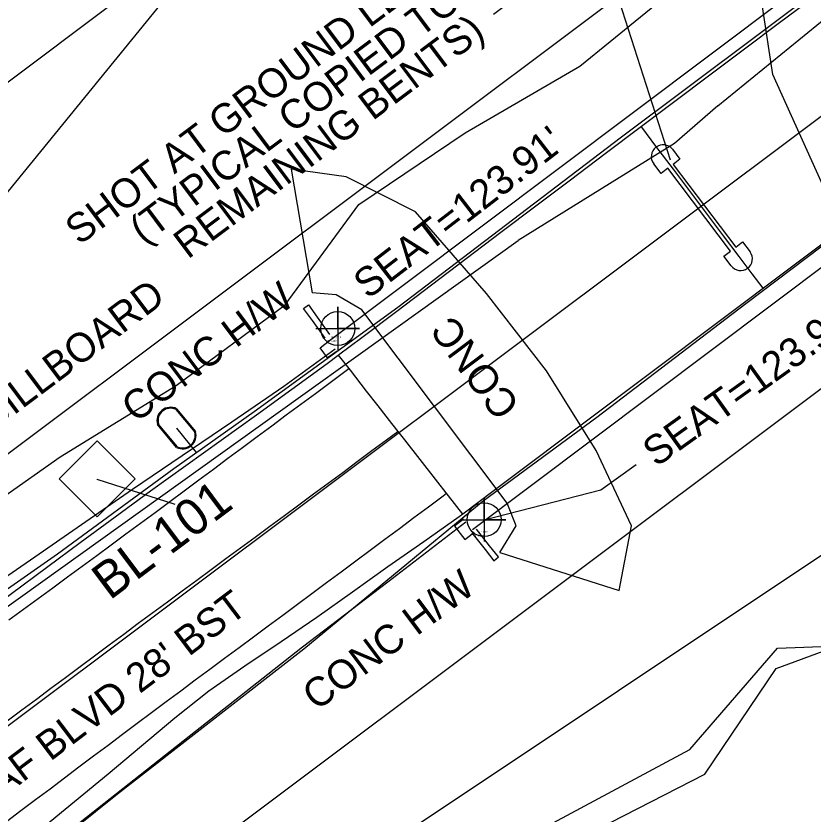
# Model space of a CAD drawing. Extents: x 2186615 to 2188822, y 629899 to 631820.
# Drawn here: x 2187538.9 to 2187648.6, y 630666.8 to 630776.8 of the extents above; entities that cross this region are included whole.
import ezdxf

# ---------------------------------------------------------------- set-up
doc = ezdxf.new("R2010")
doc.units = 0
for name, color, linetype in [('CTL Secondary Horizontal and Vertical CELL', 7, 'Continuous'), ('CTL Secondary Horizontal and Vertical Text', 7, 'Continuous'), ('CTL Vertical Benchmark Leader', 7, 'Continuous'), ('Exist Environmental Wetland Boundary', 7, 'Continuous'), ('Exist Guardrail', 7, 'Continuous'), ('Exist Horizontal Alignment', 7, 'Continuous'), ('Exist Hydro Jurisdictional Stream or Body of Water', 7, 'Continuous'), ('Exist Hydro Stream or Body of Water', 7, 'Continuous'), ('Exist Other Culture Area Outline', 7, 'Continuous'), ('Exist Other Culture Area Outline Leader', 7, 'Continuous'), ('Exist Other Culture Area Outline Text', 7, 'Continuous'), ('Exist Other Culture Sign Text', 7, 'Continuous'), ('Exist Right of Way Easement Line', 7, 'Continuous'), ('Exist Right of Way Line', 7, 'Continuous'), ('Exist Roads Curbs', 7, 'Continuous'), ('Exist Roads EOP', 7, 'Continuous'), ('Exist Roads EOP Text', 7, 'Continuous'), ('Exist Roads EOT', 7, 'Continuous'), ('Exist Structure Major Bridge Seam', 7, 'Continuous'), ('Exist Structure Major Bridge Seat Cogo Point CELL', 7, 'Continuous'), ('Exist Structure Major Bridge Seat Leader', 7, 'Continuous'), ('Exist Structure Major Bridge Seat Top Elevation', 7, 'Continuous'), ('Exist Structure Major Bridge WW', 7, 'Continuous'), ('Exist Structure Major Bridge WW Cogo Comment', 7, 'Continuous'), ('Exist Structure Major Bridge WW Text', 7, 'Continuous'), ('Exist Structure Major Deck Tunnel Box Culvert', 7, 'Continuous'), ('Exist Utilities Gas UG Line SUE LOS B', 7, 'Continuous'), ('Exist Utilities Sanitary Sewer Forced Main SUE LOS B', 7, 'Continuous'), ('Exist Utilities Telephone UG FO SUE LOS B', 7, 'Continuous'), ('Exist Utilities Water Meter CELL', 7, 'Continuous'), ('Exist Utilities Water UG Line SUE LOS B', 7, 'Continuous')]:
    doc.layers.add(name, color=color, linetype=linetype)

msp = doc.modelspace()

# ---------------------------------------------------------------- linework, layer by layer
at = {"layer": 'CTL Secondary Horizontal and Vertical CELL'}
msp.add_line((2187550.03, 630712.99), (2187550.03, 630712.99), dxfattribs=at)
msp.add_lwpolyline([(2187544.82, 630713.01), (2187550.06, 630718.25), (2187555.31, 630713), (2187550.07, 630707.76)], close=True, dxfattribs=at)
at = {"layer": 'CTL Vertical Benchmark Leader'}
msp.add_line((2187550.03, 630712.99), (2187560.75, 630709.52), dxfattribs=at)
at = {"layer": 'Exist Environmental Wetland Boundary'}
msp.add_lwpolyline([(2187317.91, 630575.27), (2187346.42, 630590.06), (2187358.05, 630607.86), (2187375.02, 630623.81), (2187367.38, 630649.06), (2187358.56, 630671.73), (2187359.61, 630693.05), (2187383.09, 630714.06), (2187423.1, 630746.78), (2187442.69, 630752.31), (2187457.31, 630748.34), (2187478.61, 630729.85), (2187488.29, 630719.76), (2187508.8, 630730.52), (2187517.08, 630724.68), (2187534.78, 630748.93), (2187558.89, 630778.43), (2187554.21, 630796.36), (2187540.11, 630831.28), (2187531.55, 630860.27), (2187515.41, 630893.02), (2187492.5, 630933.33), (2187481.79, 630966.82), (2187476.92, 630985.98)], dxfattribs=at)
at = {"layer": 'Exist Guardrail'}
for points in [[(2187492.14, 630668.93), (2187506.78, 630678.73), (2187517.34, 630685.81), (2187530.14, 630694.49), (2187541.5, 630702.26), (2187554.93, 630711.6), (2187568.6, 630720.88), (2187575.75, 630725.78), (2187582.83, 630730.92)], [(2187600.82, 630707.03), (2187590.08, 630698.8), (2187578.34, 630689.84), (2187562.72, 630677.51), (2187547.73, 630665.68), (2187531.87, 630653.17), (2187514.82, 630639.34), (2187500.32, 630627.65), (2187485.34, 630615.46), (2187477.41, 630609.1), (2187466.89, 630601.03), (2187451.76, 630589.34), (2187434.11, 630575.84), (2187413.64, 630560.33)]]:
    msp.add_lwpolyline(points, dxfattribs=at)
at = {"layer": 'Exist Horizontal Alignment'}
msp.add_line((2187136.41, 630378.11), (2188520.86, 631416.04), dxfattribs=at)
at = {"layer": 'Exist Hydro Jurisdictional Stream or Body of Water'}
for points in [[(2187685.21, 630670.03), (2187676.46, 630688.92), (2187667.73, 630709.8), (2187657.08, 630737.8), (2187643.12, 630768.72), (2187641.56, 630778.99)], [(2187449.56, 630557.04), (2187457.67, 630561.55), (2187469.6, 630560.19), (2187477.83, 630568.81), (2187483.29, 630570.83), (2187487.27, 630573.49), (2187494.84, 630580), (2187501.28, 630583.62), (2187529.01, 630602.42), (2187543.47, 630612.86), (2187569.07, 630628.39), (2187588.84, 630647.49), (2187600.3, 630658.9), (2187631.69, 630675.75), (2187643.77, 630689.68), (2187651.01, 630689.99), (2187663.15, 630692.5)], [(2187633.75, 630672.36), (2187643.56, 630686.91), (2187650.93, 630689.62), (2187663.86, 630688.82), (2187677.92, 630676.75), (2187685.21, 630670.03)], [(2187447.83, 630554.37), (2187455.66, 630557.6), (2187469.6, 630555.05), (2187473.86, 630558.86), (2187485.6, 630566.69), (2187490.63, 630573.04), (2187490.78, 630573.03), (2187503.45, 630582.34), (2187528.93, 630598.21), (2187547.35, 630610.71), (2187554.69, 630615.02), (2187566.17, 630622.44), (2187570.59, 630621.55), (2187578.03, 630632.5), (2187587.26, 630641.63), (2187602.46, 630652.89), (2187618.95, 630664.76), (2187633.75, 630672.36)]]:
    msp.add_lwpolyline(points, dxfattribs=at)
at = {"layer": 'Exist Hydro Stream or Body of Water'}
msp.add_line((2187643.56, 630686.91), (2187650.93, 630689.62), dxfattribs=at)
at = {"layer": 'Exist Other Culture Area Outline'}
for p, q in [((2187629.28, 630758.4), (2187630.31, 630757.04)), ((2187627.71, 630755.07), (2187626.7, 630756.41)), ((2187630.31, 630757.04), (2187629.37, 630756.33)), ((2187629.37, 630756.33), (2187638, 630744.94)), ((2187628.66, 630755.79), (2187627.71, 630755.07)), ((2187637.29, 630744.39), (2187628.66, 630755.79)), ((2187638, 630744.94), (2187638.95, 630745.65)), ((2187638.95, 630745.65), (2187639.98, 630744.29)), ((2187636.35, 630743.68), (2187637.29, 630744.39)), ((2187637.36, 630742.34), (2187636.35, 630743.68)), ((2187601.49, 630705.27), (2187601.97, 630705.66))]:
    msp.add_line(p, q, dxfattribs=at)
for points in [[(2187605.53, 630702.86), (2187621.96, 630697.63), (2187623.64, 630706.53), (2187618.78, 630716.92), (2187611.96, 630727.88), (2187603.68, 630738.56), (2187593.88, 630749.79), (2187584.36, 630754.61), (2187576.76, 630755.68), (2187579.69, 630738.64)], [(2187605.53, 630702.86), (2187607.77, 630706.55), (2187606.54, 630709.67), (2187586.53, 630736.3), (2187582.99, 630738.34), (2187579.69, 630738.64)], [(2187581.78, 630729.66), (2187580.75, 630731.05), (2187582.05, 630732.05)], [(2187599.25, 630706.5), (2187600.69, 630704.66), (2187601.49, 630705.27)]]:
    msp.add_lwpolyline(points, dxfattribs=at)
for centre, start, end in [((2187628, 630757.39), 38.2035, 217.1439), ((2187638.66, 630743.33), 217.1439, 36.0842)]:
    msp.add_arc(centre, 1.63, start, end, dxfattribs=at)
at = {"layer": 'Exist Other Culture Area Outline Leader'}
msp.add_lwpolyline([(2187629.01, 630756.89), (2187619.09, 630787.81), (2187604.65, 630776.98)], dxfattribs=at)
at = {"layer": 'Exist Right of Way Easement Line'}
msp.add_line((2187510.45, 630747.15), (2187623.11, 630831.8), dxfattribs=at)
at = {"layer": 'Exist Right of Way Line'}
for p, q in [((2187118.41, 630402.11), (2188502.83, 631440.02)), ((2187154.4, 630354.1), (2188538.85, 631392.04)), ((2187522.53, 630617.66), (2187850.44, 630836.28))]:
    msp.add_line(p, q, dxfattribs=at)
at = {"layer": 'Exist Roads Curbs'}
for p, q in [((2187583.13, 630730.61), (2187581.78, 630729.66)), ((2187600.52, 630707.45), (2187599.25, 630706.5))]:
    msp.add_line(p, q, dxfattribs=at)
at = {"layer": 'Exist Roads EOP'}
for points in [[(2187509.05, 630675.82), (2187513.94, 630679.3), (2187518.81, 630682.81), (2187523.65, 630686.35), (2187528.47, 630689.92), (2187533.28, 630693.5), (2187538.1, 630697.09), (2187543.26, 630700.95), (2187547.73, 630704.24), (2187552.56, 630707.8), (2187557.41, 630711.34), (2187562.27, 630714.85), (2187567.15, 630718.34), (2187572.02, 630721.85), (2187576.88, 630725.36), (2187581.73, 630728.9), (2187583.27, 630730.05)], [(2187600.43, 630708.15), (2187599.93, 630707.78), (2187595.03, 630704.32), (2187590.11, 630700.89), (2187585.22, 630697.41), (2187580.33, 630693.93), (2187575.38, 630690.55), (2187570.39, 630687.21), (2187565.46, 630683.79), (2187560.75, 630680.07), (2187556.17, 630676.2), (2187551.57, 630672.34), (2187546.96, 630668.51), (2187542.31, 630664.71)]]:
    msp.add_lwpolyline(points, dxfattribs=at)
at = {"layer": 'Exist Roads EOT'}
for points in [[(2187537.91, 630693.58), (2187539.92, 630695.06), (2187541.94, 630696.54), (2187543.95, 630698.02), (2187545.97, 630699.5), (2187547.98, 630700.98), (2187550, 630702.46), (2187552.01, 630703.94), (2187554.03, 630705.42), (2187556.04, 630706.91), (2187558.05, 630708.39), (2187560.06, 630709.88), (2187562.06, 630711.37), (2187564.07, 630712.86), (2187566.08, 630714.36), (2187568.08, 630715.85), (2187570.09, 630717.34), (2187572.1, 630718.83), (2187574.1, 630720.32), (2187576.11, 630721.81), (2187578.11, 630723.3), (2187580.12, 630724.79), (2187582.13, 630726.28), (2187584.72, 630728.22)], [(2187537.68, 630679.69), (2187539.68, 630681.18), (2187541.69, 630682.67), (2187543.69, 630684.17), (2187545.7, 630685.66), (2187547.7, 630687.16), (2187549.71, 630688.65), (2187551.71, 630690.14), (2187553.72, 630691.63), (2187555.73, 630693.12), (2187557.74, 630694.61), (2187559.75, 630696.09), (2187561.76, 630697.58), (2187563.77, 630699.06), (2187565.78, 630700.55), (2187567.8, 630702.03), (2187569.81, 630703.51), (2187571.82, 630705), (2187573.83, 630706.48), (2187575.84, 630707.97), (2187577.85, 630709.45), (2187579.86, 630710.94), (2187581.87, 630712.43), (2187583.88, 630713.91), (2187585.89, 630715.41), (2187587.89, 630716.9), (2187589.9, 630718.39), (2187591.47, 630719.55)], [(2187598.18, 630710.99), (2187597.69, 630710.63), (2187595.69, 630709.13), (2187593.68, 630707.64), (2187591.68, 630706.14), (2187589.68, 630704.64), (2187587.67, 630703.15), (2187585.67, 630701.66), (2187583.66, 630700.17), (2187581.65, 630698.68), (2187579.64, 630697.19), (2187577.63, 630695.7), (2187575.63, 630694.21), (2187573.62, 630692.72), (2187571.61, 630691.23), (2187569.6, 630689.74), (2187567.59, 630688.25), (2187565.59, 630686.77), (2187563.58, 630685.28), (2187561.57, 630683.79), (2187559.56, 630682.29), (2187557.56, 630680.8), (2187555.56, 630679.31), (2187553.56, 630677.81), (2187551.56, 630676.31), (2187549.56, 630674.8), (2187547.56, 630673.3), (2187545.56, 630671.8), (2187543.57, 630670.29), (2187541.57, 630668.79), (2187539.57, 630667.28), (2187537.58, 630665.77)]]:
    msp.add_lwpolyline(points, dxfattribs=at)
at = {"layer": 'Exist Structure Major Bridge Seam'}
msp.add_lwpolyline([(2187625, 630761.46), (2187626.97, 630758.85), (2187629.37, 630755.66), (2187631.58, 630752.72), (2187633.93, 630749.6), (2187636.28, 630746.49), (2187638.41, 630743.66), (2187640.22, 630741.26), (2187641.71, 630739.27)], dxfattribs=at)
at = {"layer": 'Exist Structure Major Bridge Seat Cogo Point CELL'}
for points in [[(2187580.19, 630733.71), (2187586.19, 630733.71), (2187583.19, 630733.71), (2187583.19, 630736.71), (2187583.19, 630730.71)], [(2187600.35, 630707.39), (2187606.35, 630707.39), (2187603.35, 630707.39), (2187603.35, 630710.39), (2187603.35, 630704.39)]]:
    msp.add_lwpolyline(points, dxfattribs=at)
for centre in [(2187583.19, 630733.71), (2187603.35, 630707.39)]:
    msp.add_circle(centre, 2.34, dxfattribs=at)
at = {"layer": 'Exist Structure Major Bridge Seat Leader'}
msp.add_lwpolyline([(2187603.35, 630707.39), (2187619.4, 630711.51), (2187624.27, 630715.01)], dxfattribs=at)
at = {"layer": 'Exist Structure Major Bridge WW'}
for points in [[(2187581.45, 630732.41), (2187579.71, 630734.81), (2187578.48, 630736.48), (2187579.16, 630736.99), (2187580.36, 630735.29), (2187582.08, 630732.89)], [(2187601.68, 630705.59), (2187603.49, 630703.3), (2187604.7, 630701.72), (2187605.33, 630702.26), (2187604.08, 630703.8), (2187602.3, 630706.09)]]:
    msp.add_lwpolyline(points, dxfattribs=at)
at = {"layer": 'Exist Structure Major Deck Tunnel Box Culvert'}
for p, q in [((2187582.05, 630732.05), (2187832.7, 630920.52)), ((2187852.33, 630894.37), (2187601.73, 630705.99))]:
    msp.add_line(p, q, dxfattribs=at)
for points in [[(2187583.31, 630730.08), (2187586.53, 630732.49), (2187591.31, 630736.12), (2187596.09, 630739.75), (2187600.88, 630743.37), (2187605.66, 630746.99), (2187610.45, 630750.6), (2187615.24, 630754.21), (2187620.03, 630757.83), (2187624.82, 630761.44), (2187629.62, 630765.05), (2187634.41, 630768.65), (2187639.21, 630772.25), (2187644.01, 630775.86), (2187648.81, 630779.46)], [(2187652.69, 630747.43), (2187647.89, 630743.83), (2187643.09, 630740.23), (2187638.3, 630736.62), (2187633.5, 630733.02), (2187628.7, 630729.42), (2187623.9, 630725.83), (2187619.1, 630722.22), (2187614.31, 630718.61), (2187609.52, 630715), (2187604.72, 630711.39), (2187600.44, 630708.16)], [(2187600.43, 630708.16), (2187598.46, 630710.67), (2187596.65, 630712.99), (2187594.53, 630715.7), (2187592.44, 630718.37), (2187591.71, 630719.31), (2187590.66, 630720.64), (2187588.77, 630723.06), (2187587.16, 630725.11), (2187584.94, 630727.96), (2187583.29, 630730.07)]]:
    msp.add_lwpolyline(points, dxfattribs=at)
at = {"layer": 'Exist Utilities Gas UG Line SUE LOS B'}
for points in [[(2187575.93, 630736.98), (2187586.1, 630750.78), (2187600.76, 630760.67), (2187616.54, 630769.83), (2187633.26, 630783.47)], [(2187331.5, 630558.33), (2187350.48, 630574.64), (2187366.06, 630585.39), (2187385.35, 630600.96), (2187399.96, 630613.56), (2187408.38, 630621.06), (2187423.17, 630631.14), (2187433.3, 630638.42), (2187450.84, 630651.54), (2187467.47, 630664.54), (2187481.97, 630676.06), (2187497.43, 630684.47), (2187517.99, 630697.1), (2187529.05, 630704.83), (2187544.97, 630716.05), (2187560.92, 630725.86), (2187575.93, 630736.98)]]:
    msp.add_lwpolyline(points, dxfattribs=at)
at = {"layer": 'Exist Utilities Sanitary Sewer Forced Main SUE LOS B'}
msp.add_lwpolyline([(2187442.18, 630656.68), (2187443.57, 630654.02), (2187450.8, 630648.53), (2187457.87, 630639.18), (2187476.15, 630615.58), (2187480.17, 630611.22), (2187493.05, 630621.78), (2187508.78, 630634.21), (2187523.23, 630645.86), (2187552.85, 630669.64), (2187578.51, 630689.58), (2187603.2, 630710), (2187618.89, 630721.49), (2187639.4, 630737.18), (2187658.16, 630751.34)], dxfattribs=at)
at = {"layer": 'Exist Utilities Telephone UG FO SUE LOS B'}
for points in [[(2187635.53, 630764.37), (2187677.66, 630798.79), (2187723.32, 630833.53), (2187763.18, 630864.29), (2187783.47, 630878.54), (2187785.72, 630883.08)], [(2187635.53, 630764.37), (2187629.57, 630759.19), (2187608.06, 630745.86)], [(2187221.79, 630477.44), (2187244.49, 630488.55), (2187260.77, 630497.3), (2187273.17, 630505), (2187293.43, 630515), (2187319.92, 630532.54), (2187378.48, 630575.93), (2187483.97, 630656.58), (2187503.96, 630671.26), (2187608.06, 630745.86)]]:
    msp.add_lwpolyline(points, dxfattribs=at)
at = {"layer": 'Exist Utilities Water Meter CELL'}
msp.add_line((2187561, 630720.01), (2187561, 630720.01), dxfattribs=at)
for points in [[(2187560.9, 630722.57), (2187563.51, 630719.44)], [(2187561, 630722.66), (2187563.61, 630719.53)], [(2187561, 630717.35), (2187558.38, 630720.5)], [(2187561.11, 630717.44), (2187558.48, 630720.59)]]:
    msp.add_lwpolyline(points, dxfattribs=at)
for centre, radius, start, end in [((2187560.16, 630721.01), 1.86, 63.0155, 195.8169), ((2187560.17, 630721), 1.73, 65.1384, 193.6198), ((2187561.83, 630719.01), 1.86, 243.4858, 16.1458), ((2187561.84, 630719), 1.73, 244.9646, 14.7103)]:
    msp.add_arc(centre, radius, start, end, dxfattribs=at)
at = {"layer": 'Exist Utilities Water UG Line SUE LOS B'}
msp.add_line((2187561, 630720.01), (2187563.68, 630716.62), dxfattribs=at)
msp.add_lwpolyline([(2187356.85, 630563.99), (2187378.55, 630580.27), (2187392.02, 630590.2), (2187407.32, 630601.82), (2187422.62, 630614.3), (2187442.82, 630630.04), (2187465.16, 630649.35), (2187481.46, 630660.64), (2187503.4, 630674.82), (2187521.29, 630686.41), (2187544.6, 630702.68), (2187560.64, 630714.46), (2187571.68, 630722.27), (2187591.48, 630736.67), (2187622.28, 630760.13), (2187641.11, 630774.22), (2187678.52, 630802.38)], dxfattribs=at)

# ---------------------------------------------------------------- texts
at = {"layer": 'CTL Secondary Horizontal and Vertical Text'}
msp.add_text('BL-101', height=5, rotation=36.8593, dxfattribs=at).set_placement((2187551.8, 630696.21))
at = {"layer": 'Exist Other Culture Area Outline Text'}
for s, rotation, p in [('SHOT AT GROUND LEVEL', 36.8593, (2187547.61, 630745.11)), ('(TYPICAL COPIED TO ', 36.8593, (2187556.48, 630745.2)), ('REMAINING BENTS)', 36.8593, (2187562.55, 630743.19)), ('CONC', 126.8593, (2187608.42, 630723.17))]:
    msp.add_text(s, height=4, rotation=rotation, dxfattribs=at).set_placement(p)
at = {"layer": 'Exist Other Culture Sign Text'}
msp.add_text('BILLBOARD', height=4, rotation=36.8593, dxfattribs=at).set_placement((2187535.69, 630719.56))
at = {"layer": 'Exist Roads EOP Text'}
msp.add_text("US 301/NC 96/S BRIGHTLEAF BLVD 28' BST", height=4, rotation=37.1238, dxfattribs=at).set_placement((2187482.93, 630628.1))
at = {"layer": 'Exist Structure Major Bridge Seat Top Elevation'}
for s, rotation, p in [("SEAT=123.91'", 37.6062, (2187587.35, 630737.66)), ("SEAT=123.94'", 35.6136, (2187627.06, 630714.55))]:
    msp.add_text(s, height=4, rotation=rotation, dxfattribs=at).set_placement(p)
at = {"layer": 'Exist Structure Major Bridge WW Cogo Comment'}
for s, p in [('BL*3119', (2187581.7, 630731.91)), ('EL*3119', (2187582.33, 630732.39)), ('EL*3119', (2187602.55, 630705.59)), ('BL*3119', (2187601.93, 630705.09))]:
    msp.add_text(s, height=0.25, dxfattribs=at).set_placement(p)
at = {"layer": 'Exist Structure Major Bridge WW Text'}
for p in [(2187555.38, 630720.63), (2187580.28, 630680.97)]:
    msp.add_text('CONC H/W', height=4, rotation=36.8593, dxfattribs=at).set_placement(p)

doc.saveas('drawing.dxf')
